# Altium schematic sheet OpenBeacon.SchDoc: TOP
size A4; CompanyName: Bitmanufactory Ltd.; DrawnBy: Brita Meriac; Engineer: Milosch Meriac; Revision: 0.1; SheetNumber: 1; SheetTotal: 1; CompanyURL: http://www.bitmanufactory.com; Project: OpenBeacon Proximity Tag BL
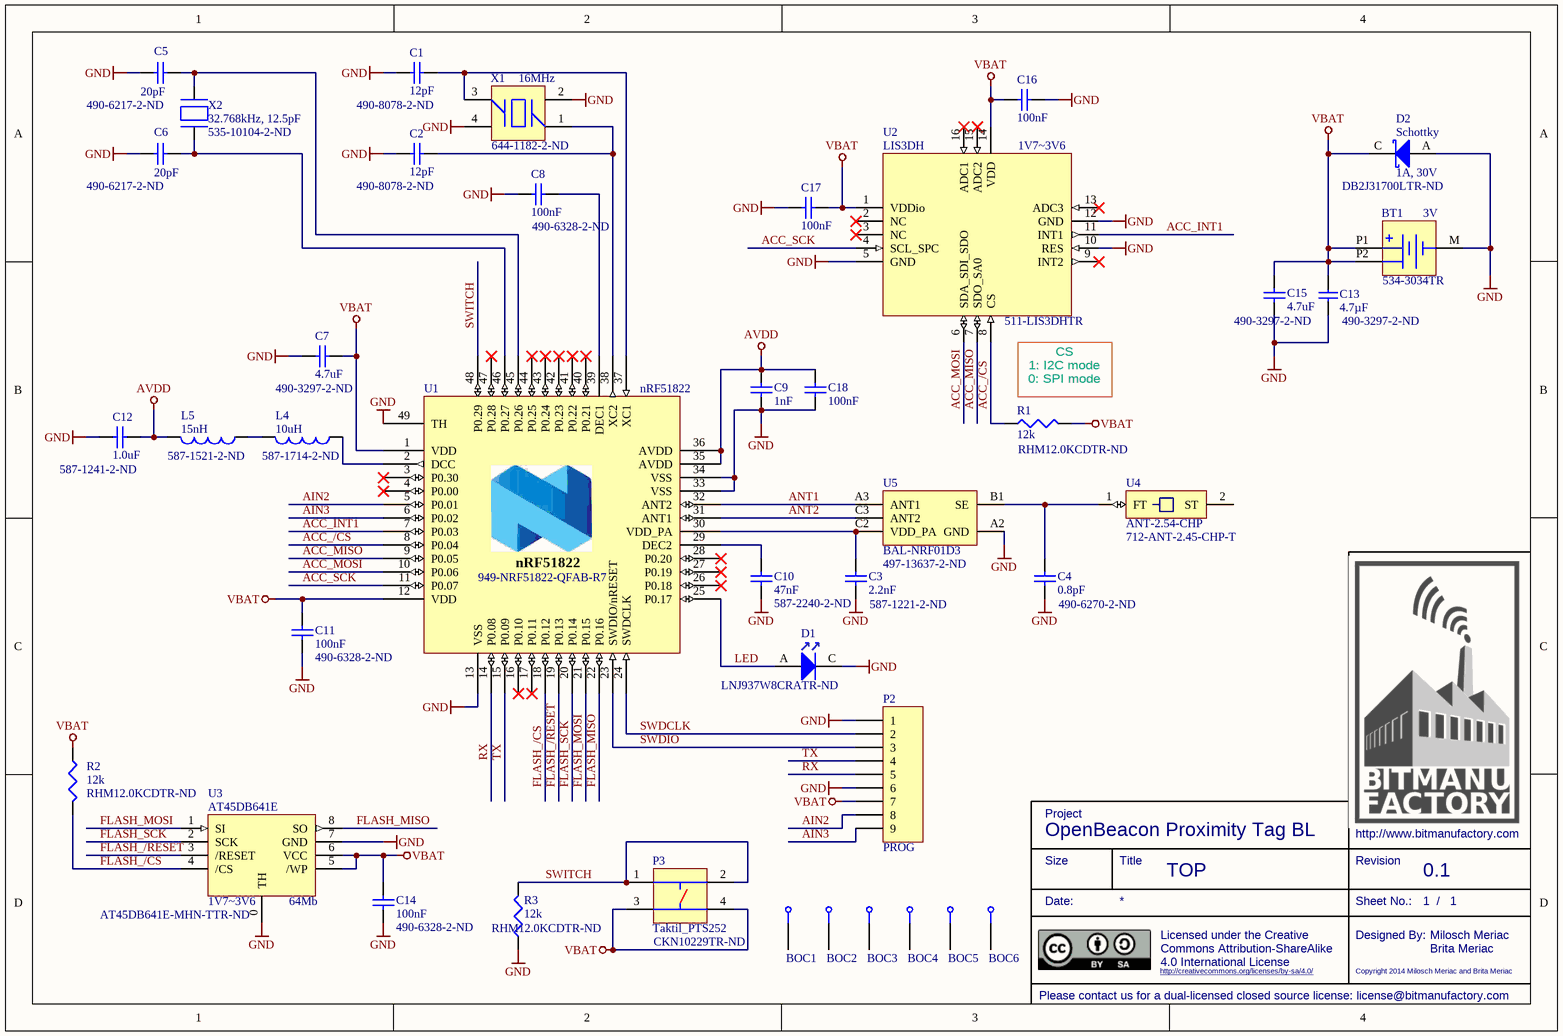
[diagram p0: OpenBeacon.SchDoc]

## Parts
BOC1  Testpad  [TESTPAD_1MM]  (value not drawn)
BOC2  Testpad  [TESTPAD_1MM]  (value not drawn)
BOC3  Testpad  [TESTPAD_1MM]  (value not drawn)
BOC4  Testpad  [TESTPAD_1MM]  (value not drawn)
BOC5  Testpad  [TESTPAD_1MM]  (value not drawn)
BOC6  Testpad  [TESTPAD_1MM]  (value not drawn)
BT1  value 3V  Supplier Part Number 1: 534-3034TR  [BAT-Holder_3034]  (hidden comment: Battery Cell Holder)
C1  Supplier Part Number 1: 490-8078-2-ND  [0402[1005]]  (hidden comment: 12pF)
C2  Supplier Part Number 1: 490-8078-2-ND  [0402[1005]]  (hidden comment: 12pF)
C3  Supplier Part Number 1: 587-1221-2-ND  [0402[1005]]  (hidden comment: 2.2nF)
C4  Supplier Part Number 1: 490-6270-2-ND  [0402[1005]]  (hidden comment: 0.8pF)
C5  value 20pF  Supplier Part Number 1: 490-6217-2-ND  [0402[1005]]  (hidden comment: Cap 20pF)
C6  value 20pF  Supplier Part Number 1: 490-6217-2-ND  [0402[1005]]  (hidden comment: Cap 20pF)
C7  Supplier Part Number 1: 490-3297-2-ND  [0603[1608]_a]  (hidden comment: 4.7uF)
C8  Supplier Part Number 1: 490-6328-2-ND  [0402[1005]]  (hidden comment: 100nF)
C9  1nF  [0402[1005]]
C10  Supplier Part Number 1: 587-2240-2-ND  [0402[1005]]  (hidden comment: 47nF)
C11  Supplier Part Number 1: 490-6328-2-ND  [0402[1005]]  (hidden comment: 100nF)
C12  Supplier Part Number 1: 587-1241-2-ND  [0603[1608]_a]  (hidden comment: 1.0uF)
C13  4.7µF  Supplier Part Number 1: 490-3297-2-ND  [0603[1608]_a]
C14  Supplier Part Number 1: 490-6328-2-ND  [0402[1005]]  (hidden comment: 100nF)
C15  Supplier Part Number 1: 490-3297-2-ND  [0603[1608]_a]  (hidden comment: 4.7uF)
C16  100nF  [0402[1005]]
C17  100nF  [0402[1005]]
C18  100nF  [0402[1005]]
D1  Supplier Part Number 1: LNJ937W8CRATR-ND  [LED_0603]  (hidden comment: LED blue)
D2  Schottky  value 1A, 30V  Supplier Part Number 1: DB2J31700LTR-ND  [SC-90A]
L4  Supplier Part Number 1: 587-1714-2-ND  [0603[1608]_a]  (hidden comment: 10uH)
L5  Supplier Part Number 1: 587-1521-2-ND  [0402[1005]]  (hidden comment: 15nH)
P2  PROG  [HDR1X9_round_custom-SMD]
P3  Taktil_PTS252  Supplier Part Number 1: CKN10229TR-ND  [taktil_PTS525]
R1  Supplier Part Number 1: RHM12.0KCDTR-ND  [0402[1005]]  (hidden comment: 12k)
R2  Supplier Part Number 1: RHM12.0KCDTR-ND  [0402[1005]]  (hidden comment: 12k)
R3  Supplier Part Number 1: RHM12.0KCDTR-ND  [0402[1005]]  (hidden comment: 12k)
U1  nRF51822  Supplier Part Number 1: 949-NRF51822-QFAB-R7  [QFN-48]
U2  LIS3DH  supply voltage: 1V7~3V6  Supplier Part Number 1: 511-LIS3DHTR  [LGA-16]
U3  AT45DB641E  value 64Mb  supply voltage: 1V7~3V6  Supplier Part Number 1: AT45DB641E-MHN-TTR-ND  [UDFN-8MA1]
U4  ANT-2.54-CHP  Supplier Part Number 1: 712-ANT-2.45-CHP-T  [ANT-CHP_rainsun]
U5  BAL-NRF01D3  Supplier Part Number 1: 497-13637-2-ND  [BAL-NRF01D3]
X1  value 16MHz  Supplier Part Number 1: 644-1182-2-ND  [SMD3225]  (hidden comment: XTAL_4Pin)
X2  value 32.768kHz, 12.5pF  Supplier Part Number 1: 535-10104-2-ND  [ABS06]  (hidden comment: XTAL-2pin)

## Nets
AVDD: C9.1 C12.1 C18.1 L5.2 U1.35(AVDD) U1.36(AVDD)
GND: BT1.M C1.2 C2.2 C3.2 C4.2 C5.1 C6.1 C7.2 C8.2 C9.2 C10.2 C11.2 C12.2 C13.1 C14.2 C15.2 C16.1 C17.2 C18.2 D1.C(Cathode) D2.A(Anode) P2.1 P2.6 R3.2 U1.13(VSS) U1.33(VSS) U1.34(VSS) U1.49(TH) U2.5(GND) U2.10(RES) U2.12(GND) U3.0(TH) U3.7(GND) U5.A2(GND) X1.2 X1.4
VBAT: BT1.P1 BT1.P2 C7.1 C11.1 C13.2 C14.1 C15.1 C16.2 C17.1 D2.C(Cathode) P2.7 P3.3 P3.4 R1.2 R2.1 U1.1(VDD) U1.12(VDD) U2.1(VDDio) U2.14(VDD) U3.5(/WP) U3.6(VCC)
ACC_/CS: R1.1 U1.8(P0.04) U2.8(CS)
ACC_INT1: U1.7(P0.03) U2.11(INT1)
ACC_MISO: U1.9(P0.05) U2.7(SDO_SA0)
ACC_MOSI: U1.10(P0.06) U2.6(SDA_SDI_SDO)
ACC_SCK: U1.11(P0.07) U2.4(SCL_SPC)
AIN2: P2.8 U1.5(P0.01)
AIN3: P2.9 U1.6(P0.02)
ANT1: U1.32(ANT2) U5.A3(ANT1)
ANT2: U1.31(ANT1) U5.C3(ANT2)
FLASH_/CS: R2.2 U1.18(P0.12) U3.4(/CS)
FLASH_/RESET: U1.19(P0.13) U3.3(/RESET)
FLASH_MISO: U1.22(P0.16) U3.8(SO)
FLASH_MOSI: U1.21(P0.15) U3.1(SI)
FLASH_SCK: U1.20(P0.14) U3.2(SCK)
LED: D1.A(Anode) U1.25(P0.17)
RX: P2.5 U1.14(P0.08)
SWDCLK: P2.2 U1.24(SWDCLK)
SWDIO: P2.3 U1.23(SWDIO/nRESET)
SWITCH: P3.1 P3.2 R3.1 U1.48(P0.29)
TX: P2.4 U1.15(P0.09)
NetC1_1: C1.1 U1.37(XC1) X1.3
NetC2_1: C2.1 U1.38(XC2) X1.1
NetC3_1: C3.1 U1.30(VDD_PA) U5.C2(VDD_PA)
NetC4_1: C4.1 U4.1(FT) U5.B1(SE)
NetC5_2: C5.2 U1.45(P0.26) X2.2
NetC6_2: C6.2 U1.46(P0.27) X2.1
NetC8_1: C8.1 U1.39(DEC1)
NetC10_1: C10.1 U1.29(DEC2)
NetL4_1: L4.1 U1.2(DCC)
NetL4_2: L4.2 L5.1

Not connected (* = marked no-connect by the designer): BOC1 1; BOC2 1; BOC3 1; BOC4 1; BOC5 1; BOC6 1; U1 3(P0.30)* 4(P0.00)* 16(P0.10)* 17(P0.11)* 26(P0.18)* 27(P0.19)* 28(P0.20)* 40(P0.21)* 41(P0.22)* 42(P0.23)* 43(P0.24)* 44(P0.25)* 47(P0.28)*; U2 2(NC)* 3(NC)* 9(INT2)* 13(ADC3)* 15(ADC2)* 16(ADC1)*; U4 2(ST)

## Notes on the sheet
- CS
  1: I2C mode
  0: SPI mode
- Project
- Date:
- Size
- Title
- Sheet No.:
- Revision
- /
- Licensed under the Creative Commons Attribution-ShareAlike 4.0 International License
- http://creativecommons.org/licenses/by-sa/4.0/
- Designed By:
- Copyright 2014 Milosch Meriac and Brita Meriac
- Please contact us for a dual-licensed closed source license: license@bitmanufactory.com

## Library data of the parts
BT1 = Battery_Cell: Battery Cell
C1 C2 = Cap Semi: Capacitor (Semiconductor SIM Model); tolerance: 2%, NPO; note: 50V
C3 C9 = Cap Semi: Capacitor (Semiconductor SIM Model); tolerance: X7R, ±10%; note: 50V
C4 = Cap Semi: Capacitor (Semiconductor SIM Model); tolerance: NP0, ±5%; note: 50V
C5 C6 = Cap Semi: Capacitor (Semiconductor SIM Model)
C7 C15 = Cap Semi: Capacitor (Semiconductor SIM Model); tolerance: X5R, ±10%; note: 6V3
C8 C11 C12 C14 C16-C18 = Cap Semi: Capacitor (Semiconductor SIM Model); tolerance: 10%, X7R; note: 16V
C10 = Cap Semi: Capacitor (Semiconductor SIM Model); tolerance: X7R, ±10%; note: 25V
C13 = C0603-4µ7: Capacitor, X5R, ±10%; Note: 6.3V; Artikkelnr Noca: 20069060
D1 = LED: value: 20mA
D2 = Diode_Shottky: Schottky barrier diode
L4 = COIL: Inductor / Spule; tolerance: 10%; note: I_DC-min=80mA
L5 = COIL: Inductor / Spule; tolerance: 5%; note: I_DC-min=320mA
P2 = Header 9: Header, 9-Pin
P3 = Taktil_PTS252: Taster
R1-R3 = Res: Resistor; tolerance: 1%; note: 0.063W
U2 = LIS3DH: LIS3DH, MEMS digital output motion sensor
U3 = AT45DB641E: serial interface Flash memory (1.7V-3.6V)
U4 = ANT-CHP: ANT-2.54-CHP, 2.45GHz Ultra-Compact Chip Antenna
U5 = BAL-NRF01D3: ST BAL-NRF01D31
X1 = XTAL_4Pin: ABM8 ceramic crystal
X2 = XTAL_2Pin: Crystal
